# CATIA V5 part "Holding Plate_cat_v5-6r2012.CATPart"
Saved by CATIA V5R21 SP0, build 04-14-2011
Part number: Holding Plate
Bounding box of the stored display mesh (mm): x -16 to 16, y -16 to 16, z 0 to 7
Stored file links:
  D:\CATIA V5R21 E-RESOURCES\CATIA-V5R21\catia-v5r21-Tut\c16-catia-v5r21-tut\c16-catia-v5r21-tut01\Holding Plate_cat_v5r21.CATPart
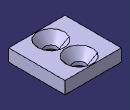
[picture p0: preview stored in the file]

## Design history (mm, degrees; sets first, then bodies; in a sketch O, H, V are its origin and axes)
Body1 (main body)
  Sketch1 on xy-plane, origin (0, 0, 0), H (1, 0, 0), V (0, 1, 0)
    line L1 (-16, 16) -> (16, 16)
    line L2 (16, 16) -> (16, -16)
    line L3 (16, -16) -> (-16, -16)
    line L4 (-16, -16) -> (-16, 16)
    construction line L5 (-16, 16) -> (16, -16)
    length L2 = 32
    length L3 = 32
    distance H L3 = 16
    distance V L4 = 16
    horizontal: L1 H, L3 H
    vertical: L2 V, L4 V
  Pad1: profile Sketch1, direction (0, 0, 1), length 7
  Sketch2 on face of Pad1, origin (-0.9262, 8.6399, 7), H (1, 0, 0), V (0, 1, 0)
    point P1 (0.9262, -0.6399)
    reference intersected line E1 through (0.9262, 0) direction (0, 1) from yz-plane
    reference projected line E3 (-15.0738, 7.3601) -> (16.9262, 7.3601) from edge of Pad1
    distance P1 E3 = 8
    coincidence: E1 P1
  Hole1: placed by Sketch2, at (0, 8, 7) direction (0, 0, -1), diameter 7, depth 10, countersink depth 5, countersink angle 80
  Mirror1: of Hole1, about zx-plane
